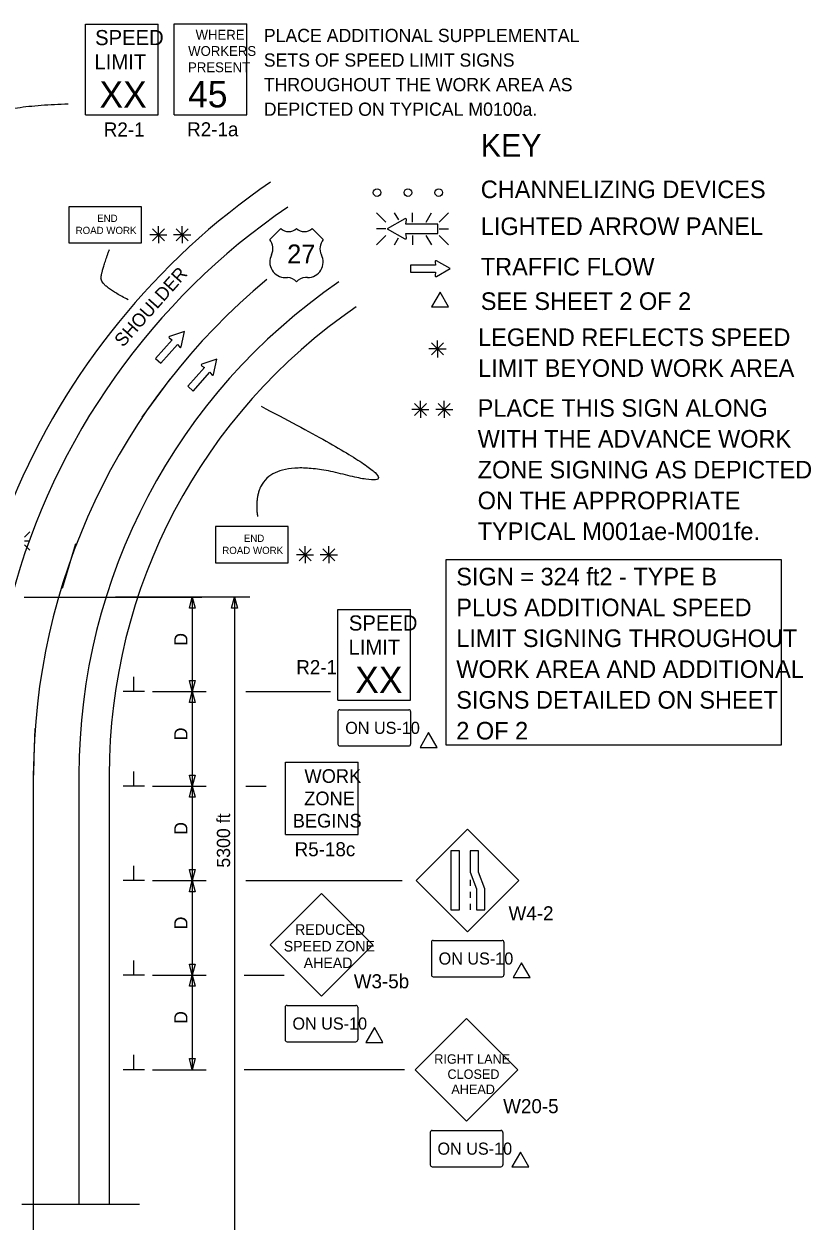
# Model space of a CAD drawing. Extents: x 16729 to 18475, y 5718 to 6974.
# Drawn here: x 17013 to 17429, y 6289 to 6922 of the extents above; entities that cross this region are included whole.
import ezdxf

# ---------------------------------------------------------------- set-up
doc = ezdxf.new("R2010")
doc.units = 0
for name, color, linetype in [('ALI_LEGAL_EX', 7, 'Continuous'), ('MT_SCRATCH_LEVEL_E', 7, 'Continuous'), ('PAVT_EDGE_EX', 7, 'Continuous'), ('TRAFFIC_SIGNS_PR', 7, 'Continuous'), ('TYPICAL_EX', 7, 'Continuous'), ('TYPICAL_TEXT_DIMEN_EX', 7, 'Continuous'), ('TYPICAL_TEXT_DIMEN_PR', 7, 'Continuous')]:
    doc.layers.add(name, color=color, linetype=linetype)

msp = doc.modelspace()

# ---------------------------------------------------------------- linework, layer by layer
at = {"layer": 'ALI_LEGAL_EX'}
for p, q in [((17039.84, 6647.53), (17032.85, 6623.88)), ((17017.65, 6024.8), (17017.65, 6525.15))]:
    msp.add_line(p, q, dxfattribs=at)
for points in [[(17075.14, 6714.42), (17089.89, 6734.61)], [(17017.7, 6524.8), (17017.65, 6525.15), (17018.48, 6549.78)], [(17017.65, 6424.8), (17017.65, 6449.8)], [(17017.7, 6349.8), (17017.7, 6374.8)]]:
    msp.add_lwpolyline(points, dxfattribs=at)
msp.add_arc((17357.65, 6525.15), 340, 129.56655, 180, dxfattribs=at)
at = {"layer": 'MT_SCRATCH_LEVEL_E'}
for p, q in [((17230.34, 6794.85), (17217.09, 6794.85)), ((17217.09, 6794.85), (17217.09, 6791.11)), ((17230.03, 6796.63), (17230.34, 6794.85)), ((17237.95, 6793), (17230.71, 6797.11)), ((17217.09, 6791.11), (17230.34, 6791.11)), ((17230.34, 6791.11), (17230.03, 6789.33)), ((17230.71, 6788.85), (17237.95, 6793)), ((17089.5, 6756.28), (17091.04, 6755.33)), ((17097.48, 6759.79), (17089.6, 6757.11)), ((17095.77, 6751.62), (17097.48, 6759.79)), ((17091.04, 6755.33), (17082.24, 6745.42)), ((17085.03, 6742.93), (17093.84, 6752.84)), ((17093.84, 6752.84), (17094.96, 6751.43)), ((17082.24, 6745.42), (17085.03, 6742.93)), ((17114.56, 6745.13), (17106.68, 6742.45)), ((17112.85, 6736.96), (17114.56, 6745.13)), ((17108.12, 6740.67), (17099.32, 6730.76)), ((17102.12, 6728.28), (17110.92, 6738.19)), ((17106.59, 6741.62), (17108.12, 6740.67)), ((17110.92, 6738.19), (17112.04, 6736.77)), ((17099.32, 6730.76), (17102.12, 6728.28))]:
    msp.add_line(p, q, dxfattribs=at)
for centre, start, end in [((17230.49, 6796.7), 60.42484, 189.96381), ((17230.49, 6789.26), 170.03619, 299.77312), ((17089.75, 6756.67), 108.80279, 238.34176), ((17095.31, 6751.73), 218.41415, 348.15107), ((17106.84, 6742.01), 108.80279, 238.34176), ((17112.4, 6737.07), 218.41415, 348.15107)]:
    msp.add_arc(centre, 0.463, start, end, dxfattribs=at)
at = {"layer": 'PAVT_EDGE_EX'}
for p, q in [((17041.65, 6525.15), (17041.65, 6298.02)), ((17057.65, 6525.15), (17057.65, 6298.02))]:
    msp.add_line(p, q, dxfattribs=at)
for radius, start, end in [(380, 124.38118, 157.50106), (364, 124.38118, 165.0045), (316, 124.38117, 180), (300, 124.38117, 180), (300, 180, 180.00000277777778)]:
    msp.add_arc((17357.65, 6525.15), radius, start, end, dxfattribs=at)
at = {"layer": 'TRAFFIC_SIGNS_PR'}
for p, q in [((17045.21, 6922.33), (17083.61, 6922.33)), ((17045.21, 6874.33), (17045.21, 6922.33)), ((17083.61, 6874.33), (17083.61, 6922.33)), ((17092.08, 6922.42), (17130.48, 6922.42)), ((17092.08, 6874.42), (17092.08, 6922.42)), ((17130.48, 6874.42), (17130.48, 6922.42)), ((17045.21, 6874.33), (17083.61, 6874.33)), ((17092.08, 6874.42), (17130.48, 6874.42)), ((17199.02, 6822.58), (17203.95, 6817.65)), ((17210.78, 6818.76), (17208.57, 6822.58)), ((17218.1, 6817.65), (17218.1, 6822.58)), ((17225.34, 6817.65), (17228.19, 6822.58)), ((17232.25, 6817.65), (17237.19, 6822.58)), ((17203.95, 6814.09), (17199.02, 6814.09)), ((17232.25, 6814.09), (17237.19, 6814.09)), ((17199.02, 6805.6), (17203.95, 6810.53)), ((17208.53, 6805.6), (17210.64, 6809.26)), ((17218.1, 6810.53), (17218.1, 6805.6)), ((17228.23, 6805.6), (17225.38, 6810.53)), ((17232.25, 6810.53), (17237.19, 6805.6)), ((17012.91, 6651.01), (17015.73, 6653.83)), ((17012.91, 6648.97), (17015.73, 6648.97)), ((17012.91, 6646.94), (17015.73, 6644.12)), ((17178.67, 6612.74), (17217.07, 6612.74)), ((17178.67, 6564.74), (17178.67, 6612.74)), ((17217.07, 6564.74), (17217.07, 6612.74)), ((17178.67, 6564.74), (17217.07, 6564.74)), ((17179.67, 6559.74), (17216.07, 6559.74)), ((17178.67, 6558.74), (17178.67, 6541.54)), ((17217.07, 6558.74), (17217.07, 6541.54)), ((17179.67, 6540.54), (17216.07, 6540.54)), ((17150.94, 6493.66), (17150.94, 6532.06)), ((17150.94, 6532.06), (17189.34, 6532.06)), ((17189.34, 6493.66), (17189.34, 6532.06)), ((17247.26, 6496.48), (17220.11, 6469.33)), ((17274.41, 6469.33), (17247.26, 6496.48)), ((17150.94, 6493.66), (17189.34, 6493.66)), ((17220.11, 6469.33), (17247.26, 6442.17)), ((17247.26, 6442.17), (17274.41, 6469.33)), ((17248.5, 6469.82), (17248.5, 6466.62)), ((17169.93, 6462.5), (17142.77, 6435.34)), ((17197.08, 6435.34), (17169.93, 6462.5)), ((17248.5, 6463.42), (17248.5, 6460.22)), ((17248.5, 6457.02), (17248.5, 6453.82)), ((17142.77, 6435.34), (17169.93, 6408.19)), ((17169.93, 6408.19), (17197.08, 6435.34)), ((17228.06, 6436.73), (17228.06, 6419.53)), ((17229.06, 6437.73), (17265.46, 6437.73)), ((17266.46, 6436.73), (17266.46, 6419.53)), ((17229.06, 6418.53), (17265.46, 6418.53)), ((17150.75, 6402.34), (17150.75, 6385.14)), ((17151.75, 6403.34), (17188.15, 6403.34)), ((17189.15, 6402.34), (17189.15, 6385.14)), ((17246.66, 6396.48), (17219.51, 6369.33)), ((17273.81, 6369.33), (17246.66, 6396.48)), ((17151.75, 6384.14), (17188.15, 6384.14)), ((17219.51, 6369.33), (17246.66, 6342.18)), ((17246.66, 6342.18), (17273.81, 6369.33)), ((17227.46, 6336.18), (17227.46, 6318.98)), ((17228.46, 6337.18), (17264.86, 6337.18)), ((17265.86, 6336.18), (17265.86, 6318.98)), ((17228.46, 6317.98), (17264.86, 6317.98))]:
    msp.add_line(p, q, dxfattribs=at)
for points in [[(17036.34, 6806.58), (17074.74, 6806.58), (17074.74, 6825.78), (17036.34, 6825.78)], [(17113.9, 6637.34), (17152.3, 6637.34), (17152.3, 6656.54), (17113.9, 6656.54)], [(17238.37, 6485.06), (17238.37, 6453.82), (17242.86, 6453.82), (17242.86, 6485.06)], [(17248.5, 6485.06), (17248.5, 6473.88), (17251.85, 6465), (17251.85, 6453.82), (17256.34, 6453.82), (17256.34, 6465), (17252.99, 6473.88), (17252.99, 6485.06)]]:
    msp.add_lwpolyline(points, close=True, dxfattribs=at)
for points in [[(17214.03, 6819.37), (17204.74, 6814.09), (17214.03, 6808.77)], [(17214.9, 6809.4), (17214.5, 6811.66), (17231.52, 6811.66), (17231.52, 6816.47), (17214.5, 6816.47), (17214.91, 6818.75)]]:
    msp.add_lwpolyline(points, dxfattribs=at)
for centre in [(17199.36, 6833.24), (17215.66, 6833.24), (17231.96, 6833.24)]:
    msp.add_circle(centre, 2, dxfattribs=at)
for centre, radius, start, end in [((17214.32, 6818.84), 0.598, 350.73078, 118.89165), ((17214.32, 6809.29), 0.597, 241.48329, 9.95933), ((17179.67, 6558.74), 1, 90, 180), ((17216.07, 6558.74), 1, 0, 90), ((17179.67, 6541.54), 1, 180, 270), ((17216.07, 6541.54), 1, 270, 0), ((17229.06, 6436.73), 1, 90, 180), ((17265.46, 6436.73), 1, 0, 90), ((17229.06, 6419.53), 1, 180, 270), ((17265.46, 6419.53), 1, 270, 0), ((17151.75, 6402.34), 1, 90, 180), ((17188.15, 6402.34), 1, 0, 90), ((17151.75, 6385.14), 1, 180, 270), ((17188.15, 6385.14), 1, 270, 0), ((17228.46, 6336.18), 1, 90, 180), ((17264.86, 6336.18), 1, 0, 90), ((17228.46, 6318.98), 1, 180, 270), ((17264.86, 6318.98), 1, 270, 0)]:
    msp.add_arc(centre, radius, start, end, dxfattribs=at)
at = {"layer": 'TYPICAL_EX'}
for p, q in [((17142.58, 6808.34), (17148.47, 6814.24)), ((17170.88, 6808.34), (17164.98, 6814.24)), ((17150.83, 6788.28), (17152, 6788.28)), ((17162.63, 6788.28), (17161.45, 6788.28))]:
    msp.add_line(p, q, dxfattribs=at)
for centre, radius, start, end in [((17152.6, 6818.53), 5.96, 226.14041, 313.85958), ((17160.86, 6818.53), 5.96, 226.14042, 313.85959), ((17136.99, 6803.62), 7.31, 333.09768, 40.19361), ((17176.46, 6803.62), 7.31, 139.80639, 206.90233), ((17150.84, 6796.53), 8.24, 152.6698, 269.90132), ((17162.62, 6796.53), 8.24, 270.09868, 27.3302), ((17152.02, 6782.38), 5.91, 37.1038, 90.13853), ((17161.44, 6782.38), 5.91, 89.86147, 142.8962)]:
    msp.add_arc(centre, radius, start, end, dxfattribs=at)
at = {"layer": 'TYPICAL_TEXT_DIMEN_EX'}
msp.add_lwpolyline([(17235.92, 6639.11), (17413.13, 6639.11), (17413.13, 6540.92), (17235.92, 6540.92)], close=True, dxfattribs=at)
at = {"layer": 'TYPICAL_TEXT_DIMEN_PR'}
for p, q in [((17080.57, 6814.14), (17086.95, 6807.76)), ((17086.95, 6814.14), (17080.57, 6807.76)), ((17083.76, 6810.95), (17083.76, 6815.41)), ((17093.13, 6814.14), (17099.5, 6807.76)), ((17099.5, 6814.14), (17093.13, 6807.76)), ((17096.32, 6810.95), (17096.32, 6815.41)), ((17083.76, 6810.95), (17079.23, 6810.95)), ((17083.76, 6810.95), (17086.95, 6810.95)), ((17083.76, 6810.95), (17088.24, 6810.95)), ((17083.76, 6810.95), (17083.76, 6806.45)), ((17096.32, 6810.95), (17091.78, 6810.95)), ((17096.32, 6810.95), (17099.5, 6810.95)), ((17096.32, 6810.95), (17100.79, 6810.95)), ((17096.32, 6810.95), (17096.32, 6806.45)), ((17231.33, 6750.55), (17226.8, 6750.55)), ((17228.14, 6753.74), (17234.52, 6747.36)), ((17234.52, 6753.74), (17228.14, 6747.36)), ((17231.33, 6750.55), (17231.33, 6755.01)), ((17231.33, 6750.55), (17234.52, 6750.55)), ((17231.33, 6750.55), (17235.81, 6750.55)), ((17231.33, 6750.55), (17231.33, 6746.05)), ((17222.33, 6718.58), (17217.79, 6718.58)), ((17219.14, 6721.76), (17225.51, 6715.39)), ((17225.51, 6721.76), (17219.14, 6715.39)), ((17222.33, 6718.58), (17222.33, 6723.03)), ((17222.33, 6718.58), (17225.51, 6718.58)), ((17222.33, 6718.58), (17226.8, 6718.58)), ((17222.33, 6718.58), (17222.33, 6714.08)), ((17234.88, 6718.58), (17230.35, 6718.58)), ((17231.69, 6721.76), (17238.07, 6715.39)), ((17238.07, 6721.76), (17231.69, 6715.39)), ((17234.88, 6718.58), (17234.88, 6723.03)), ((17234.88, 6718.58), (17238.07, 6718.58)), ((17234.88, 6718.58), (17239.36, 6718.58)), ((17234.88, 6718.58), (17234.88, 6714.08)), ((17161.32, 6641.72), (17156.79, 6641.72)), ((17158.13, 6644.9), (17164.51, 6638.53)), ((17164.51, 6644.9), (17158.13, 6638.53)), ((17161.32, 6641.72), (17161.32, 6646.17)), ((17161.32, 6641.72), (17164.51, 6641.72)), ((17161.32, 6641.72), (17165.8, 6641.72)), ((17161.32, 6641.72), (17161.32, 6637.22)), ((17173.87, 6641.72), (17169.34, 6641.72)), ((17170.69, 6644.9), (17177.06, 6638.53)), ((17177.06, 6644.9), (17170.69, 6638.53)), ((17173.87, 6641.72), (17173.87, 6646.17)), ((17173.87, 6641.72), (17177.06, 6641.72)), ((17173.87, 6641.72), (17178.35, 6641.72)), ((17173.87, 6641.72), (17173.87, 6637.22)), ((17012.72, 6619.33), (17106.65, 6619.33)), ((17132.09, 6619.33), (17060.95, 6619.33)), ((17100.08, 6613.47), (17101.65, 6619.33)), ((17101.65, 6619.33), (17103.22, 6613.47)), ((17101.65, 6619.33), (17101.65, 6569.33)), ((17122.44, 6613.47), (17124.01, 6619.33)), ((17124.01, 6619.33), (17124.01, 6235.65)), ((17124.01, 6619.33), (17125.58, 6613.47)), ((17101.65, 6613.47), (17100.08, 6613.47)), ((17103.22, 6613.47), (17101.65, 6613.47)), ((17124.01, 6613.47), (17122.44, 6613.47)), ((17125.58, 6613.47), (17124.01, 6613.47)), ((17070.77, 6569.33), (17070.77, 6577.11)), ((17101.65, 6569.33), (17100.08, 6575.19)), ((17100.08, 6575.19), (17101.65, 6575.19)), ((17101.65, 6575.19), (17103.22, 6575.19)), ((17103.22, 6575.19), (17101.65, 6569.33)), ((17076.4, 6569.33), (17065.15, 6569.33)), ((17080.65, 6569.33), (17109.05, 6569.33)), ((17100.08, 6563.47), (17101.65, 6569.33)), ((17101.65, 6569.33), (17101.65, 6519.33)), ((17101.65, 6569.33), (17103.22, 6563.47)), ((17129.98, 6569.33), (17174.68, 6569.33)), ((17101.65, 6563.47), (17100.08, 6563.47)), ((17103.22, 6563.47), (17101.65, 6563.47)), ((17070.77, 6519.33), (17070.77, 6527.11)), ((17101.65, 6519.33), (17100.08, 6525.19)), ((17100.08, 6525.19), (17101.65, 6525.19)), ((17101.65, 6525.19), (17103.22, 6525.19)), ((17103.22, 6525.19), (17101.65, 6519.33)), ((17076.4, 6519.33), (17065.15, 6519.33)), ((17080.65, 6519.33), (17109.05, 6519.33)), ((17100.08, 6513.47), (17101.65, 6519.33)), ((17101.65, 6519.33), (17101.65, 6469.33)), ((17101.65, 6519.33), (17103.22, 6513.47)), ((17129.98, 6519.33), (17140.65, 6519.33)), ((17101.65, 6513.47), (17100.08, 6513.47)), ((17103.22, 6513.47), (17101.65, 6513.47)), ((17070.77, 6469.33), (17070.77, 6477.11)), ((17101.65, 6469.33), (17100.08, 6475.19)), ((17100.08, 6475.19), (17101.65, 6475.19)), ((17101.65, 6475.19), (17103.22, 6475.19)), ((17103.22, 6475.19), (17101.65, 6469.33)), ((17076.4, 6469.33), (17065.15, 6469.33)), ((17080.65, 6469.33), (17109.05, 6469.33)), ((17100.08, 6463.47), (17101.65, 6469.33)), ((17101.65, 6469.33), (17101.65, 6419.33)), ((17101.65, 6469.33), (17103.22, 6463.47)), ((17129.98, 6469.33), (17212.65, 6469.33)), ((17101.65, 6463.47), (17100.08, 6463.47)), ((17103.22, 6463.47), (17101.65, 6463.47)), ((17070.77, 6419.33), (17070.77, 6427.11)), ((17101.65, 6419.33), (17100.08, 6425.19)), ((17100.08, 6425.19), (17101.65, 6425.19)), ((17101.65, 6425.19), (17103.22, 6425.19)), ((17103.22, 6425.19), (17101.65, 6419.33)), ((17076.4, 6419.33), (17065.15, 6419.33)), ((17080.65, 6419.33), (17109.05, 6419.33)), ((17100.08, 6413.47), (17101.65, 6419.33)), ((17101.65, 6419.33), (17101.65, 6369.33)), ((17101.65, 6419.33), (17103.22, 6413.47)), ((17129, 6419.33), (17150.23, 6419.33)), ((17101.65, 6413.47), (17100.08, 6413.47)), ((17103.22, 6413.47), (17101.65, 6413.47)), ((17070.77, 6369.33), (17070.77, 6377.11)), ((17101.65, 6369.33), (17100.08, 6375.19)), ((17100.08, 6375.19), (17101.65, 6375.19)), ((17101.65, 6375.19), (17103.22, 6375.19)), ((17103.22, 6375.19), (17101.65, 6369.33)), ((17076.4, 6369.33), (17065.15, 6369.33)), ((17080.65, 6369.33), (17109.05, 6369.33)), ((17213.91, 6369.33), (17129, 6369.33)), ((17073.79, 6298.02), (17011.46, 6298.02))]:
    msp.add_line(p, q, dxfattribs=at)
for points in [[(17232.66, 6780.63), (17228.14, 6772.79), (17237.19, 6772.79)], [(17226.62, 6547.6), (17222.1, 6539.77), (17231.15, 6539.77)], [(17275.76, 6425.91), (17271.24, 6418.07), (17280.29, 6418.07)], [(17197.95, 6391.59), (17193.43, 6383.76), (17202.48, 6383.76)], [(17275.16, 6325.75), (17270.64, 6317.92), (17279.69, 6317.92)]]:
    msp.add_lwpolyline(points, close=True, dxfattribs=at)
for points in [[(17036.03, 6880.07), (16939.73, 6876.74), (17023.71, 6782.03), (16940.29, 6788.65)], [(17067.74, 6776.56), (17052.9, 6784), (17053.84, 6792.31), (17057.8, 6803.09)], [(17138.01, 6720.2), (17233.21, 6670.88), (17131.63, 6697.14), (17136.1, 6661.91)]]:
    msp.add_open_spline(points, degree=2, dxfattribs=at)

# ---------------------------------------------------------------- texts
at = {"layer": 'TRAFFIC_SIGNS_PR'}
for s, height, p in [('SPEED', 8, (17050.24, 6911.2)), ('WHERE', 5.2, (17103.39, 6914.11)), ('PLACE ADDITIONAL SUPPLEMENTAL', 7, (17139.44, 6912.83)), ('WORKERS', 5.2, (17099.46, 6905.51)), ('LIMIT', 8, (17049.91, 6898.4)), ('PRESENT', 5.2, (17099.39, 6896.91)), ('SETS OF SPEED LIMIT SIGNS', 7, (17139.44, 6899.83)), ('XX', 14.031, (17052.52, 6878.09)), ('45', 14.031, (17099.38, 6878.28)), ('THROUGHOUT THE WORK AREA AS', 7, (17139.44, 6886.83)), ('DEPICTED ON TYPICAL M0100a.', 7, (17139.44, 6873.83)), ('R2-1', 7.44, (17054.82, 6862.89)), ('R2-1a', 7.44, (17098.93, 6862.98)), ('END', 3.831, (17051.34, 6817.71)), ('ROAD WORK', 3.831, (17039.95, 6811.32)), ('PLACE THIS SIGN ALONG', 9.3, (17252.56, 6714.65)), ('WITH THE ADVANCE WORK', 9.3, (17252.56, 6698.35)), ('ZONE SIGNING AS DEPICTED', 9.3, (17252.56, 6682.05)), ('ON THE APPROPRIATE', 9.3, (17252.56, 6665.75)), ('TYPICAL M001ae-M001fe.', 9.3, (17252.56, 6649.45)), ('END', 3.831, (17128.9, 6648.47)), ('ROAD WORK', 3.831, (17117.5, 6642.09)), ('SPEED', 8, (17184.44, 6601.6)), ('LIMIT', 8, (17184.28, 6588.8)), ('R2-1', 7.44, (17156.63, 6578.52)), ('XX', 14.031, (17187.79, 6568.5)), ('ON US-10', 6.4, (17182.51, 6546.94)), ('WORK', 7.217, (17160.94, 6521.03)), ('ZONE', 7.217, (17160.82, 6509.21)), ('BEGINS', 7.217, (17154.75, 6497.41)), ('R5-18c', 7.44, (17155.75, 6482.22)), ('W4-2', 7.441, (17268.88, 6448.32)), ('REDUCED', 5.6, (17155.98, 6440.65)), ('SPEED ZONE', 5.6, (17149.98, 6431.85)), ('AHEAD', 5.6, (17160.54, 6423.05)), ('ON US-10', 6.401, (17231.9, 6424.93)), ('W3-5b', 7.44, (17187.02, 6412.38)), ('ON US-10', 6.4, (17154.59, 6390.55)), ('RIGHT LANE', 4.999, (17229.61, 6372.48)), ('CLOSED', 4.999, (17236.59, 6364.48)), ('AHEAD', 4.999, (17238.64, 6356.49)), ('W20-5', 7.439, (17266.05, 6346.34)), ('ON US-10', 6.401, (17231.29, 6324.38))]:
    msp.add_text(s, height=height, dxfattribs=at).set_placement(p)
at = {"layer": 'TYPICAL_EX'}
msp.add_text('27', height=10, dxfattribs=at).set_placement((17151.84, 6795.77))
at = {"layer": 'TYPICAL_TEXT_DIMEN_EX'}
for s, height, p in [('KEY', 12, (17254.2, 6852.19)), ('CHANNELIZING DEVICES', 9.3, (17254.2, 6830.3)), ('LIGHTED ARROW PANEL', 9.3, (17254.2, 6810.78)), ('TRAFFIC FLOW', 9.3, (17254.2, 6789.41)), ('SEE SHEET 2 OF 2', 9.3, (17254.2, 6771.16)), ('LEGEND REFLECTS SPEED', 9.3, (17252.78, 6752.08)), ('LIMIT BEYOND WORK AREA', 9.3, (17252.78, 6735.78)), ('SIGN = 324 ft2 - TYPE B', 9.3, (17241.24, 6625.48)), ('PLUS ADDITIONAL SPEED', 9.3, (17241.24, 6609.18)), ('LIMIT SIGNING THROUGHOUT', 9.3, (17241.24, 6592.88)), ('WORK AREA AND ADDITIONAL', 9.3, (17241.24, 6576.58)), ('SIGNS DETAILED ON SHEET', 9.3, (17241.24, 6560.28)), ('2 OF 2', 9.3, (17241.24, 6543.98))]:
    msp.add_text(s, height=height, dxfattribs=at).set_placement(p)
at = {"layer": 'TYPICAL_TEXT_DIMEN_PR'}
for s, rotation, p in [('SHOULDER', 48.37803, (17065, 6751.09)), ('D', 90, (17099.09, 6593.55)), ('D', 90, (17099.09, 6543.55)), ('5300 ft', 90, (17121.62, 6476.2)), ('D', 90, (17099.09, 6493.55)), ('D', 90, (17099.09, 6443.55)), ('D', 90, (17099.09, 6393.55))]:
    msp.add_text(s, height=7, rotation=rotation, dxfattribs=at).set_placement(p)

doc.saveas('drawing.dxf')
